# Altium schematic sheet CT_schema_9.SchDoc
size 274 x 160 mm
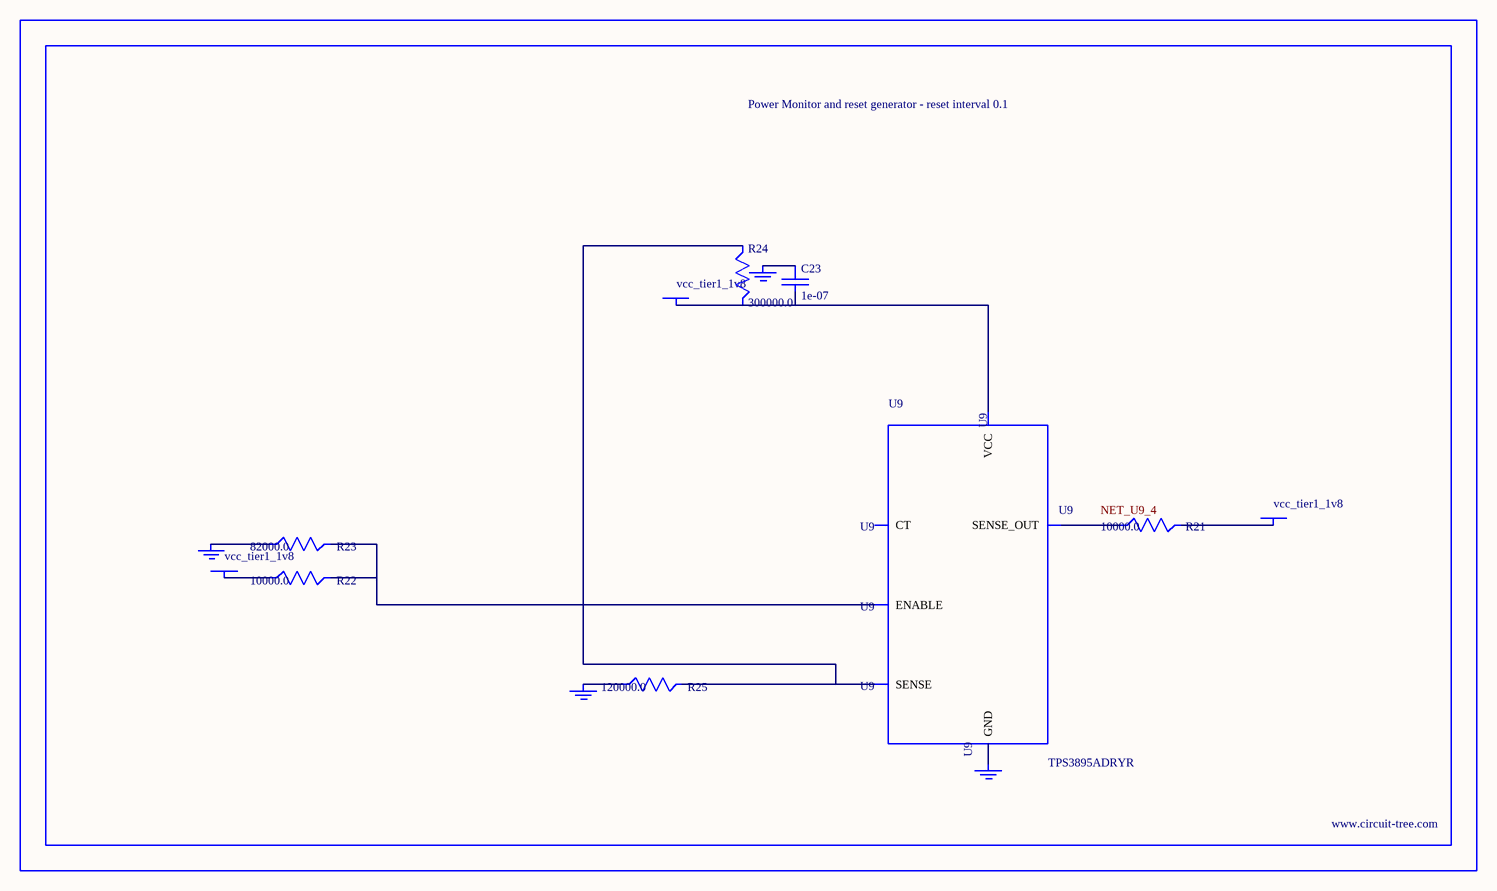
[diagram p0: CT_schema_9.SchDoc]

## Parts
BORDER8  (no value)
C23  1e-07  [C0402]
GND_INSTANCE_8_0  (no value)
GND_INSTANCE_8_1  (no value)
GND_INSTANCE_8_2  (no value)
GND_INSTANCE_8_3  (no value)
POWER_INSTANCE_8_0  vcc_tier1_1v8
POWER_INSTANCE_8_1  vcc_tier1_1v8
POWER_INSTANCE_8_2  vcc_tier1_1v8
R21  10000.0  [R0603]
R22  10000.0  [R0603]
R23  82000.0  [R0603]
R24  300000.0  [R0603]
R25  120000.0  [R0603]
U9  TPS3895ADRYR  [SON-6]

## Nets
NetC23_1: C23.1 GND_INSTANCE_8_2.0(GND)
NetC23_2: C23.2 POWER_INSTANCE_8_2.0(PWR) R24.2 U9.6(VCC)
NetGND_INSTANCE_8_0_0: GND_INSTANCE_8_0.0(GND) R23.1
NetGND_INSTANCE_8_1_0: GND_INSTANCE_8_1.0(GND) R25.1
NetGND_INSTANCE_8_3_0: GND_INSTANCE_8_3.0(GND) U9.2(GND)
NetPOWER_INSTANCE_8_0_0: POWER_INSTANCE_8_0.0(PWR) R22.1
NetPOWER_INSTANCE_8_1_0: POWER_INSTANCE_8_1.0(PWR) R21.2
NetR21_1: R21.1 U9.4(SENSE_OUT)
NetR22_2: R22.2 R23.2 U9.1(ENABLE)
NetR24_1: R24.1 R25.2 U9.3(SENSE)

Not connected (* = marked no-connect by the designer): U9 5(CT)

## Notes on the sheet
- Labels drawn without touching a wire or pin: NET_U9_4

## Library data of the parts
BORDER8 = BORDER_PAGE8
C23 = C0402C104K3RACTU
GND_INSTANCE_8_0-GND_INSTANCE_8_3 = GND
POWER_INSTANCE_8_0-POWER_INSTANCE_8_2 = PWR
R21 R22 = RC0603JR-0710KL
R23 = RC0603JR-0782KL
R24 = RC0603JR-07300KL
R25 = RC0603JR-07120KL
